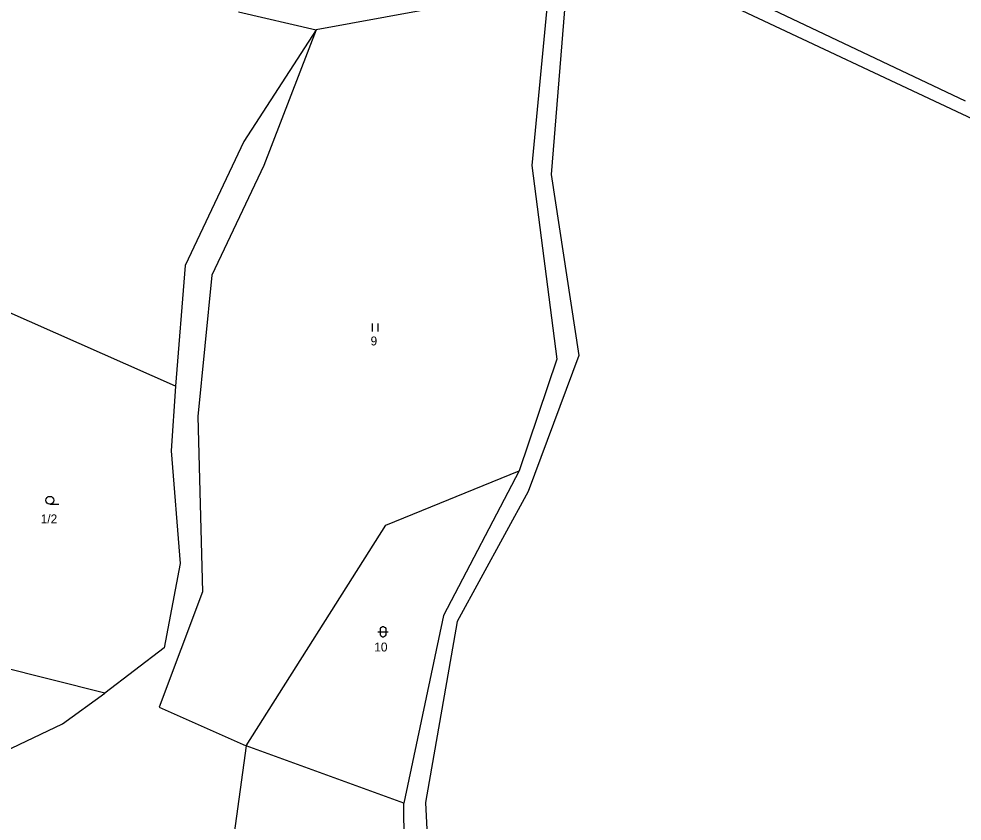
# Model space of a CAD drawing. Extents: x -794421 to -792735, y -1117671 to -1115559.
# Drawn here: x -793289.6 to -793109.5, y -1116849.4 to -1116696.2 of the extents above; entities that cross this region are included whole.
import ezdxf

# ---------------------------------------------------------------- set-up
doc = ezdxf.new("R2010")
doc.units = 0
for name, color, linetype in [('Vrstva 1', 7, 'Continuous'), ('Vrstva 14', 7, 'Continuous'), ('Vrstva 23', 7, 'Continuous')]:
    doc.layers.add(name, color=color, linetype=linetype)

msp = doc.modelspace()

# ---------------------------------------------------------------- linework, layer by layer
at = {"layer": 'Vrstva 1'}
for p, q in [((-793175.39, -1116683.36), (-793071.81, -1116732.17)), ((-793161.81, -1116686.74), (-793108.95, -1116711.9)), ((-793188.39, -1116690.17), (-793232.83, -1116698.32)), ((-793188.39, -1116690.17), (-793191.63, -1116724.21)), ((-793185.18, -1116691.38), (-793187.93, -1116725.93)), ((-793247.63, -1116694.88), (-793232.83, -1116698.32)), ((-793232.83, -1116698.32), (-793246.59, -1116719.63)), ((-793232.83, -1116698.32), (-793242.81, -1116724.22)), ((-793246.59, -1116719.63), (-793257.8, -1116743.29)), ((-793242.81, -1116724.22), (-793252.75, -1116745.12)), ((-793191.63, -1116724.21), (-793186.88, -1116761.16)), ((-793187.93, -1116725.93), (-793182.66, -1116760.49)), ((-793257.8, -1116743.29), (-793259.64, -1116766.35)), ((-793252.75, -1116745.12), (-793255.41, -1116772.15)), ((-793259.64, -1116766.35), (-793292.01, -1116752.03)), ((-793186.88, -1116761.16), (-793194.06, -1116782.47)), ((-793182.66, -1116760.49), (-793192.32, -1116786.47)), ((-793259.64, -1116766.35), (-793260.5, -1116778.66)), ((-793255.41, -1116772.15), (-793254.52, -1116805.57)), ((-793260.5, -1116778.66), (-793258.79, -1116800.2)), ((-793219.49, -1116792.86), (-793194.06, -1116782.47)), ((-793194.06, -1116782.47), (-793208.52, -1116810.13)), ((-793192.32, -1116786.47), (-793205.92, -1116811.25)), ((-793246.16, -1116834.96), (-793219.49, -1116792.86)), ((-793258.79, -1116800.2), (-793261.8, -1116816.26)), ((-793254.52, -1116805.57), (-793262.76, -1116827.6)), ((-793208.52, -1116810.13), (-793216.07, -1116845.94)), ((-793205.92, -1116811.25), (-793211.95, -1116845.79)), ((-793273.14, -1116824.93), (-793313.38, -1116814.8)), ((-793261.8, -1116816.26), (-793273.14, -1116824.93)), ((-793281.23, -1116830.79), (-793273.14, -1116824.93)), ((-793262.76, -1116827.6), (-793246.16, -1116834.96)), ((-793296.06, -1116837.88), (-793281.23, -1116830.79)), ((-793246.16, -1116834.96), (-793248.94, -1116854.97)), ((-793216.07, -1116845.94), (-793246.16, -1116834.96)), ((-793215.92, -1116876.71), (-793216.07, -1116845.94)), ((-793211.95, -1116845.79), (-793211, -1116864.23))]:
    msp.add_line(p, q, dxfattribs=at)
at = {"layer": 'Vrstva 23'}
for p, q in [((-793222.06, -1116755.9), (-793222.06, -1116754.4)), ((-793221.06, -1116754.4), (-793221.06, -1116755.9)), ((-793283.65, -1116788.87), (-793281.9, -1116788.87)), ((-793220.54, -1116812.62), (-793220.44, -1116812.42)), ((-793220.54, -1116813.82), (-793220.54, -1116812.62)), ((-793220.44, -1116812.42), (-793220.34, -1116812.32)), ((-793220.34, -1116812.32), (-793220.14, -1116812.22)), ((-793220.14, -1116812.22), (-793219.94, -1116812.22)), ((-793219.94, -1116812.22), (-793219.74, -1116812.32)), ((-793219.74, -1116812.32), (-793219.64, -1116812.42)), ((-793219.64, -1116812.42), (-793219.54, -1116812.62)), ((-793219.54, -1116812.62), (-793219.54, -1116813.82)), ((-793221.04, -1116813.22), (-793219.04, -1116813.22)), ((-793220.44, -1116814.02), (-793220.54, -1116813.82)), ((-793220.34, -1116814.12), (-793220.44, -1116814.02)), ((-793220.14, -1116814.22), (-793220.34, -1116814.12)), ((-793219.94, -1116814.22), (-793220.14, -1116814.22)), ((-793219.74, -1116814.12), (-793219.94, -1116814.22)), ((-793219.64, -1116814.02), (-793219.74, -1116814.12)), ((-793219.54, -1116813.82), (-793219.64, -1116814.02))]:
    msp.add_line(p, q, dxfattribs=at)
msp.add_circle((-793283.65, -1116788.12), 0.75, dxfattribs=at)

# ---------------------------------------------------------------- texts
at = {"layer": 'Vrstva 14'}
for s, p in [('9', (-793222.427, -1116758.56)), ('1/2', (-793285.393, -1116792.52)), ('10', (-793221.719, -1116816.98))]:
    msp.add_text(s, height=1.7, dxfattribs=at).set_placement(p)

doc.saveas('drawing.dxf')
